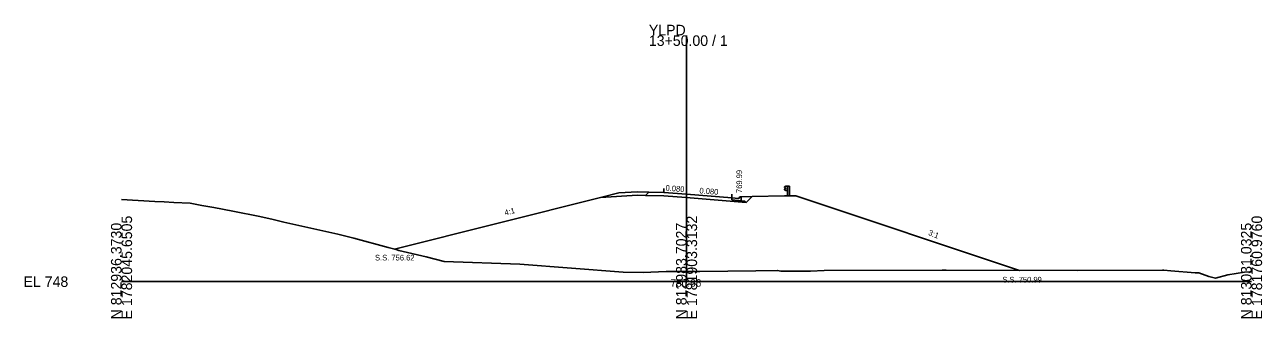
# Model space of a CAD drawing. Extents: x -26 to 353, y -10 to 9080.
# Drawn here: x -25.7 to 302.8, y 3490.3 to 3568.1 of the extents above; entities that cross this region are included whole.
import ezdxf

# ---------------------------------------------------------------- set-up
doc = ezdxf.new("R2010")
doc.units = 0
for name, color, linetype in [('Exist Cross Section Cell', 7, 'Continuous'), ('Exist XS Center Line Elevation Label', 7, 'Continuous'), ('Exist XS Ground Line', 7, 'Continuous'), ('Prop XS Dump Level', 7, 'Continuous'), ('Prop XS Earthwork Shape', 7, 'Continuous'), ('Prop XS EOT Tick Mark', 7, 'Continuous'), ('Prop XS Finish Grade', 7, 'Continuous'), ('Prop XS Finish Grade CurbGutter', 7, 'Continuous'), ('Prop XS Finish Grade Earthwork', 7, 'Continuous'), ('Prop XS Finish Grade Paved Shoulder', 7, 'Continuous'), ('Prop XS Finish Grade Pavement', 7, 'Continuous'), ('Prop XS Guardrail', 7, 'Continuous'), ('Prop XS Hydro Elevations', 7, 'Continuous'), ('Prop XS Pvmt Edge Slope', 7, 'Continuous'), ('Prop XS SE Text', 7, 'Continuous'), ('Prop XS Side Slope Text', 7, 'Continuous'), ('Prop XS SS Elevation Text', 7, 'Continuous'), ('Prop XS Subgrade CurbGutter', 7, 'Continuous'), ('Prop XS Subgrade Earthwork', 7, 'Continuous'), ('Scratch_Level_3', 7, 'Continuous')]:
    doc.layers.add(name, color=color, linetype=linetype)

msp = doc.modelspace()

# ---------------------------------------------------------------- linework, layer by layer
at = {"layer": 'Exist Cross Section Cell'}
for p, q in [((150, 3500), (150, 3565.3)), ((0, 3500), (150, 3500)), ((150, 3500), (300, 3500))]:
    msp.add_line(p, q, dxfattribs=at)
at = {"layer": 'Exist XS Ground Line'}
for p, q in [((0, 3521.77), (8.81, 3521.29)), ((8.81, 3521.29), (11.29, 3521.15)), ((11.29, 3521.15), (13.92, 3521.01)), ((13.92, 3521.01), (18.22, 3520.79)), ((18.22, 3520.79), (21.3, 3520.23)), ((21.3, 3520.23), (24.49, 3519.62)), ((24.49, 3519.62), (29.52, 3518.66)), ((29.52, 3518.66), (36.68, 3517.27)), ((36.68, 3517.27), (40.23, 3516.48)), ((40.23, 3516.48), (43.1, 3515.79)), ((43.1, 3515.79), (57.46, 3512.57)), ((57.46, 3512.57), (61.68, 3511.54)), ((61.68, 3511.54), (70.78, 3509.05)), ((70.78, 3509.05), (72.95, 3508.49)), ((72.95, 3508.49), (73.62, 3508.27)), ((73.62, 3508.27), (80.91, 3506.56)), ((80.91, 3506.56), (85.65, 3505.33)), ((85.65, 3505.33), (105.76, 3504.64)), ((105.76, 3504.64), (133.18, 3502.51)), ((133.18, 3502.51), (138.46, 3502.47)), ((138.46, 3502.47), (144.59, 3502.66)), ((144.59, 3502.66), (150, 3502.66)), ((150, 3502.66), (153.56, 3502.65)), ((153.56, 3502.65), (168.36, 3502.83)), ((168.36, 3502.83), (174.17, 3502.99)), ((174.17, 3502.99), (175.06, 3502.82)), ((175.06, 3502.82), (177.53, 3502.75)), ((177.53, 3502.75), (182.93, 3502.82)), ((182.93, 3502.82), (186.54, 3502.99)), ((186.54, 3502.99), (217.82, 3503.09)), ((217.82, 3503.09), (218.93, 3503.09)), ((218.93, 3503.09), (253.88, 3502.92)), ((253.88, 3502.92), (276.34, 3503.04)), ((276.34, 3503.04), (276.67, 3503.03)), ((276.67, 3503.03), (278.6, 3502.88)), ((278.6, 3502.88), (285.07, 3502.32)), ((285.07, 3502.32), (286.03, 3502.31)), ((286.03, 3502.31), (288.65, 3501.39)), ((293.67, 3501.78), (298.14, 3502.52)), ((298.14, 3502.52), (299.55, 3502.58)), ((299.55, 3502.58), (300, 3502.57)), ((288.65, 3501.39), (290.42, 3500.95)), ((290.42, 3500.95), (293.67, 3501.78))]:
    msp.add_line(p, q, dxfattribs=at)
at = {"layer": 'Prop XS Dump Level'}
for p, q in [((144, 3523.67), (150, 3523.19)), ((150, 3523.19), (162, 3522.23))]:
    msp.add_line(p, q, dxfattribs=at)
at = {"layer": 'Prop XS Earthwork Shape'}
msp.add_lwpolyline([(143.95, 3522.76), (139.1, 3522.85), (137.02, 3522.89), (127.17, 3522.3), (72.44, 3508.62), (72.95, 3508.49), (73.62, 3508.27), (80.91, 3506.56), (85.65, 3505.33), (105.76, 3504.64), (133.18, 3502.51), (138.46, 3502.47), (144.59, 3502.66), (150, 3502.66), (153.56, 3502.65), (168.36, 3502.83), (174.17, 3502.99), (175.06, 3502.82), (177.53, 3502.75), (182.93, 3502.82), (186.54, 3502.99), (217.82, 3503.09), (218.93, 3503.09), (238.4, 3502.99), (179, 3522.79), (176, 3522.73), (167.39, 3522.55), (165.84, 3521.01), (149.93, 3522.28)], close=True, dxfattribs=at)
at = {"layer": 'Prop XS EOT Tick Mark'}
for p, q in [((144, 3523.67), (144, 3524.67)), ((162, 3522.23), (162, 3523.23))]:
    msp.add_line(p, q, dxfattribs=at)
at = {"layer": 'Prop XS Finish Grade'}
for p, q in [((132, 3523.51), (127.17, 3522.3)), ((137, 3523.81), (132, 3523.51)), ((140, 3523.75), (137, 3523.81)), ((164.5, 3522.49), (167.39, 3522.55))]:
    msp.add_line(p, q, dxfattribs=at)
at = {"layer": 'Prop XS Finish Grade CurbGutter'}
for p, q in [((162, 3522.23), (163.75, 3522.02)), ((163.75, 3522.02), (163.87, 3522.05)), ((163.87, 3522.05), (163.97, 3522.14)), ((163.97, 3522.14), (164.03, 3522.39)), ((164.03, 3522.39), (164.12, 3522.48)), ((164.25, 3522.49), (164.12, 3522.48)), ((164.5, 3522.49), (164.25, 3522.49))]:
    msp.add_line(p, q, dxfattribs=at)
at = {"layer": 'Prop XS Finish Grade Earthwork'}
for p, q in [((127.17, 3522.3), (72.44, 3508.62)), ((167.39, 3522.55), (176, 3522.73)), ((176, 3522.73), (179, 3522.79)), ((179, 3522.79), (238.4, 3502.99))]:
    msp.add_line(p, q, dxfattribs=at)
at = {"layer": 'Prop XS Finish Grade Paved Shoulder'}
msp.add_line((144, 3523.67), (140, 3523.75), dxfattribs=at)
at = {"layer": 'Prop XS Finish Grade Pavement'}
for p, q in [((144, 3523.67), (150, 3523.19)), ((150, 3523.19), (162, 3522.23))]:
    msp.add_line(p, q, dxfattribs=at)
at = {"layer": 'Prop XS Guardrail'}
for p, q in [((176.32, 3525.31), (176.03, 3525.11)), ((176.82, 3525.31), (176.32, 3525.31)), ((177.32, 3525.31), (176.82, 3525.31)), ((176.82, 3525.31), (176.82, 3522.81)), ((177.32, 3522.81), (177.32, 3525.31)), ((176.03, 3525.11), (176, 3525.05)), ((176, 3525.05), (176.03, 3524.99)), ((176.03, 3524.5), (176, 3524.44)), ((176, 3524.44), (176.03, 3524.38)), ((176.03, 3524.99), (176.32, 3524.79)), ((176.32, 3524.7), (176.03, 3524.5)), ((176.03, 3524.38), (176.32, 3524.18)), ((176.32, 3524.79), (176.32, 3524.7)), ((176.32, 3524.18), (176.82, 3524.18))]:
    msp.add_line(p, q, dxfattribs=at)
at = {"layer": 'Prop XS Pvmt Edge Slope'}
for p, q in [((140, 3523.75), (139.1, 3522.85)), ((164.5, 3521.45), (165.5, 3521.37)), ((165.5, 3521.37), (165.84, 3521.01))]:
    msp.add_line(p, q, dxfattribs=at)
at = {"layer": 'Prop XS Subgrade CurbGutter'}
for p, q in [((162, 3522.23), (162, 3521.65)), ((164.5, 3521.45), (164.5, 3522.49)), ((162, 3521.65), (164.5, 3521.45))]:
    msp.add_line(p, q, dxfattribs=at)
at = {"layer": 'Prop XS Subgrade Earthwork'}
for p, q in [((137.02, 3522.89), (127.17, 3522.3)), ((139.1, 3522.85), (137.02, 3522.89)), ((143.95, 3522.76), (139.1, 3522.85)), ((143.95, 3522.76), (149.93, 3522.28)), ((149.93, 3522.28), (165.84, 3521.01)), ((165.84, 3521.01), (167.39, 3522.55))]:
    msp.add_line(p, q, dxfattribs=at)
at = {"layer": 'Scratch_Level_3'}
for p, q in [((132, 3523.51), (127.17, 3522.3)), ((127.17, 3522.3), (137.02, 3522.89)), ((137, 3523.81), (132, 3523.51)), ((140, 3523.75), (137, 3523.81)), ((137.02, 3522.89), (139.1, 3522.85)), ((139.1, 3522.85), (140, 3523.75))]:
    msp.add_line(p, q, dxfattribs=at)

# ---------------------------------------------------------------- texts
at = {"layer": 'Exist Cross Section Cell'}
for s, p in [('YLPD', (140, 3565.3)), ('13+50.00 / 1', (140, 3562.5)), ('EL 748', (-26, 3498.6))]:
    msp.add_text(s, height=2.8, dxfattribs=at).set_placement(p)
for s, p in [('N 812936.3730', (0, 3490)), ('E 1782045.6505', (2.8, 3490)), ('N 812983.7027', (150, 3490)), ('E 1781903.3132', (152.8, 3490)), ('N 813031.0325', (300, 3490)), ('E 1781760.9760', (302.8, 3490))]:
    msp.add_text(s, height=2.8, rotation=90, dxfattribs=at).set_placement(p)
at = {"layer": 'Exist XS Center Line Elevation Label'}
msp.add_text('750.66', height=2, dxfattribs=at).set_placement((145.73, 3498.66))
at = {"layer": 'Prop XS Dump Level'}
msp.add_text('Case4', height=0.04, dxfattribs=at).set_placement((132, 3523.47))
at = {"layer": 'Prop XS Hydro Elevations'}
msp.add_text('769.99', height=1.5, rotation=90, dxfattribs=at).set_placement((164.75, 3523.49))
at = {"layer": 'Prop XS SE Text'}
for p in [(144.38, 3524.14), (153.38, 3523.42)]:
    msp.add_text('0.080', height=1.5, rotation=355.4261, dxfattribs=at).set_placement(p)
at = {"layer": 'Prop XS Side Slope Text'}
for s, rotation, p in [('4:1', 14.0362, (101.86, 3517.52)), ('3:1', 338.101, (214.04, 3512.42))]:
    msp.add_text(s, height=1.5, rotation=rotation, dxfattribs=at).set_placement(p)
at = {"layer": 'Prop XS SS Elevation Text'}
for s, p in [('S.S. 756.62', (67.3, 3505.62)), ('S.S. 750.99', (233.84, 3499.77))]:
    msp.add_text(s, height=1.5, dxfattribs=at).set_placement(p)

doc.saveas('drawing.dxf')
